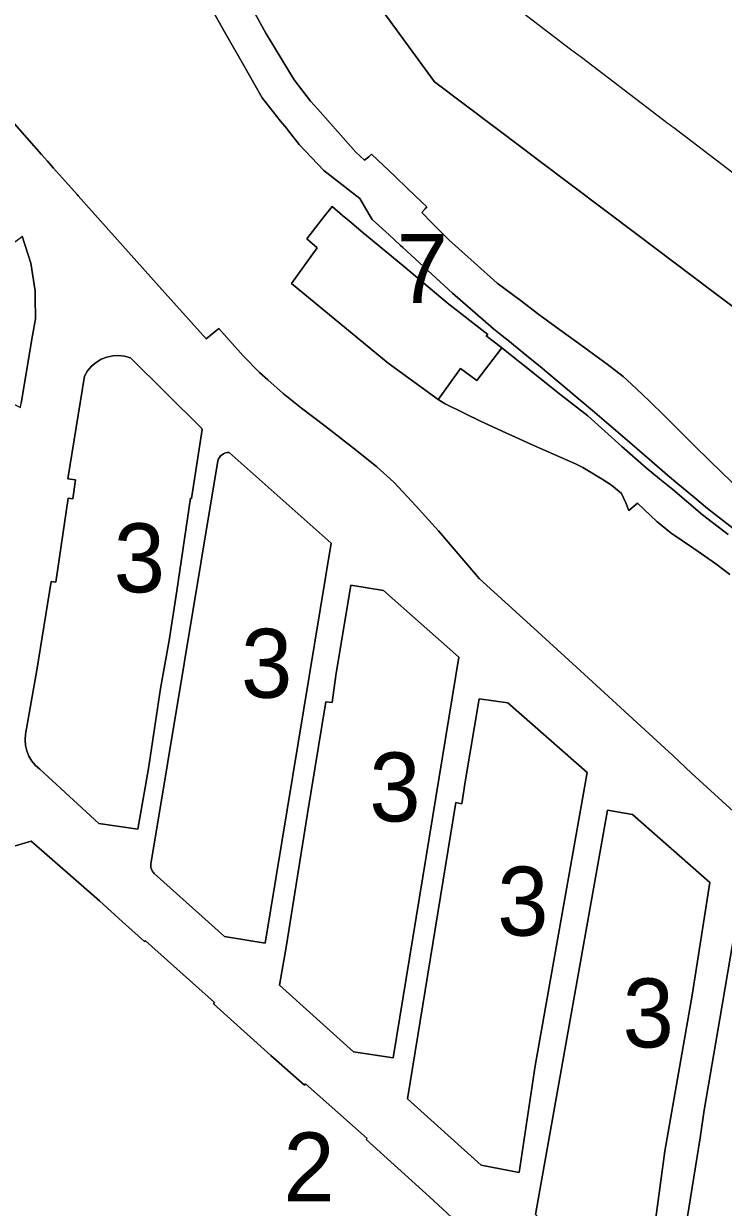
# Model space of a CAD drawing. Extents: x 598968 to 613553, y 4409678 to 4430833.
# Drawn here: x 607478.1 to 607599.8, y 4416479.9 to 4416685.8 of the extents above; entities that cross this region are included whole.
import ezdxf

# ---------------------------------------------------------------- set-up
doc = ezdxf.new("R2010")
doc.units = 0
for name, color, linetype in [('1', 7, 'Continuous'), ('ZONA 2. CARRERS DE CASES. Cases de trast', 7, 'Continuous'), ("ZONA 3. ILLES  D'EDIFICIS ENTRE MITGERES. EIXAMPLE.", 7, 'Continuous'), ('ZONA 7. CONJUNTS AMB ORDENACIONS ESPECÍFIQUES', 7, 'Continuous')]:
    doc.layers.add(name, color=color, linetype=linetype)

msp = doc.modelspace()

# ---------------------------------------------------------------- linework, layer by layer
at = {"layer": '1'}
for points in [[(607527.3672, 4416706.0991), (607549.5876, 4416675.6756), (607565.0673, 4416664.0096), (607567.5237, 4416662.1584), (607567.7321, 4416662.0015), (607584.8422, 4416649.1068), (607597.5962, 4416639.4965), (607608.9492, 4416630.9392)], [(607608.9492, 4416630.9392), (607597.5962, 4416639.4965), (607584.8422, 4416649.1068), (607567.7321, 4416662.0015), (607567.5237, 4416662.1584), (607565.0673, 4416664.0096), (607549.5876, 4416675.6756), (607527.3672, 4416706.0991)], [(607602.4415, 4416604.9807), (607599.6354, 4416607.6654), (607597.1873, 4416610.0078), (607595.0365, 4416612.131), (607592.1696, 4416615.0294), (607589.5868, 4416617.5946), (607587.0907, 4416620.0143), (607585.7848, 4416621.2802), (607583.8472, 4416623.0959), (607582.4373, 4416624.4167), (607579.6244, 4416626.5351), (607576.4249, 4416628.8801), (607576.3745, 4416628.917), (607570.7888, 4416632.9939), (607567.7575, 4416635.2064), (607564.4734, 4416637.6739), (607560.4776, 4416640.6762), (607556.4776, 4416644.2661), (607552.1594, 4416648.1558), (607550.3662, 4416649.9361), (607549.3387, 4416650.9565), (607549.1076, 4416651.1858), (607547.3976, 4416652.9658), (607547.9865, 4416653.6015), (607548.2776, 4416653.9158), (607547.3937, 4416654.7609), (607544.8997, 4416657.1461), (607542.7626, 4416659.1863), (607538.6677, 4416663.0955), (607538.1877, 4416662.6255), (607537.4077, 4416662.0455), (607535.9477, 4416663.4154), (607529.2969, 4416670.8985), (607528.0378, 4416672.3152), (607525.1978, 4416676.0151), (607520.2362, 4416684.1517), (607515.8654, 4416692.2057)], [(607515.8654, 4416692.2057), (607520.2362, 4416684.1517), (607525.1978, 4416676.0151), (607528.0378, 4416672.3152), (607529.2969, 4416670.8985), (607535.9477, 4416663.4154), (607537.4077, 4416662.0455), (607538.1877, 4416662.6255), (607538.6677, 4416663.0955), (607542.7626, 4416659.1863), (607544.8997, 4416657.1461), (607547.3937, 4416654.7609), (607548.2776, 4416653.9158), (607547.9865, 4416653.6015), (607547.3976, 4416652.9658), (607549.1076, 4416651.1858), (607549.3387, 4416650.9565), (607550.3662, 4416649.9361), (607552.1594, 4416648.1558), (607556.4776, 4416644.2661), (607560.4776, 4416640.6762), (607564.4734, 4416637.6739), (607567.7575, 4416635.2064), (607570.7888, 4416632.9939), (607576.3745, 4416628.917), (607576.4249, 4416628.8801), (607579.6244, 4416626.5351), (607582.4373, 4416624.4167), (607583.8472, 4416623.0959), (607585.7848, 4416621.2802), (607587.0907, 4416620.0143), (607589.5868, 4416617.5946), (607592.1696, 4416615.0294), (607595.0365, 4416612.131), (607597.1873, 4416610.0078), (607599.6354, 4416607.6654), (607602.4415, 4416604.9807)], [(607509.9029, 4416690.1297), (607513.2579, 4416684.0948), (607516.4329, 4416678.4949), (607519.6079, 4416672.895), (607522.8428, 4416668.8451), (607523.8895, 4416667.5348), (607523.964, 4416667.4416), (607526.0778, 4416664.7952), (607528.2128, 4416662.5153), (607530.3478, 4416660.2354), (607533.4878, 4416657.7955), (607534.0115, 4416657.3886), (607534.8207, 4416656.7598), (607536.6277, 4416655.3555), (607538.2554, 4416652.5999), (607538.7777, 4416651.7156), (607539.3614, 4416651.1822), (607541.7009, 4416649.0446), (607542.6627, 4416648.1658), (607543.6987, 4416647.2113), (607544.0839, 4416646.8564), (607552.7173, 4416638.9267), (607559.8877, 4416632.7264), (607561.2944, 4416631.5654), (607562.3662, 4416630.7129), (607565.5885, 4416628.0825), (607568.3513, 4416625.8622), (607569.1462, 4416625.1929), (607572.0004, 4416622.7896), (607574.5714, 4416620.6089), (607577.0665, 4416618.4943), (607579.9074, 4416616.0868), (607583.1155, 4416613.3085), (607585.2472, 4416611.4621), (607587.379, 4416609.6159), (607590.1373, 4416607.2271), (607591.9109, 4416605.7502), (607594.5084, 4416603.5873), (607597.1058, 4416601.4244), (607601.5051, 4416598.023)], [(607601.5051, 4416598.023), (607597.1058, 4416601.4244), (607594.5084, 4416603.5873), (607591.9109, 4416605.7502), (607590.1373, 4416607.2271), (607587.379, 4416609.6159), (607585.2472, 4416611.4621), (607583.1155, 4416613.3085), (607579.9074, 4416616.0868), (607577.0665, 4416618.4943), (607574.5714, 4416620.6089), (607572.0004, 4416622.7896), (607569.1462, 4416625.1929), (607568.3513, 4416625.8622), (607565.5885, 4416628.0825), (607562.3662, 4416630.7129), (607561.2944, 4416631.5654), (607559.8877, 4416632.7264), (607552.7173, 4416638.9267), (607544.0839, 4416646.8564), (607543.6987, 4416647.2113), (607542.6627, 4416648.1658), (607541.7009, 4416649.0446), (607539.3614, 4416651.1822), (607538.7777, 4416651.7156), (607538.2554, 4416652.5999), (607536.6277, 4416655.3555), (607534.8207, 4416656.7598), (607534.0115, 4416657.3886), (607533.4878, 4416657.7955), (607530.3478, 4416660.2354), (607528.2128, 4416662.5153), (607526.0778, 4416664.7952), (607523.964, 4416667.4416), (607523.8895, 4416667.5348), (607522.8428, 4416668.8451), (607519.6079, 4416672.895), (607516.4329, 4416678.4949), (607513.2579, 4416684.0948), (607509.9029, 4416690.1297)], [(607614.0479, 4416650.2438), (607591.2043, 4416667.6598), (607590.8733, 4416667.9122), (607590.5651, 4416668.1472), (607590.27, 4416668.3721), (607575.1528, 4416679.8974), (607573.2844, 4416681.3218), (607564.1252, 4416688.3032)], [(607606.9302, 4416543.8484), (607594.3303, 4416555.4268), (607591.0375, 4416558.4527), (607574.3176, 4416573.8472), (607566.2277, 4416581.212), (607557.4287, 4416589.2367), (607550.2878, 4416597.5465), (607548.0619, 4416600.044), (607546.4378, 4416601.8664), (607542.5078, 4416606.0563), (607539.5729, 4416608.6712), (607538.3435, 4416609.6678), (607535.5329, 4416611.9461), (607530.5529, 4416615.8009), (607526.478, 4416618.9008), (607523.268, 4416621.4708), (607520.608, 4416623.8057), (607519.178, 4416625.0956), (607516.3281, 4416627.9956), (607514.3881, 4416630.1705), (607512.1094, 4416632.7616), (607509.8781, 4416630.9454), (607501.7182, 4416640.0452), (607487.6315, 4416655.8444), (607487.4431, 4416656.0557), (607483.3545, 4416660.6414), (607482.2913, 4416661.8469), (607481.2278, 4416663.0529), (607465.8801, 4416680.4569)], [(607465.8801, 4416680.4569), (607481.2278, 4416663.0529), (607482.2913, 4416661.8469), (607483.3545, 4416660.6414), (607487.4431, 4416656.0557), (607487.6315, 4416655.8444), (607501.7182, 4416640.0452), (607509.8781, 4416630.9454), (607512.1094, 4416632.7616), (607514.3881, 4416630.1705), (607516.3281, 4416627.9956), (607519.178, 4416625.0956), (607520.608, 4416623.8057), (607523.268, 4416621.4708), (607526.478, 4416618.9008), (607530.5529, 4416615.8009), (607535.5329, 4416611.9461), (607538.3435, 4416609.6678), (607539.5729, 4416608.6712), (607542.5078, 4416606.0563), (607546.4378, 4416601.8664), (607548.0619, 4416600.044), (607550.2878, 4416597.5465), (607557.4287, 4416589.2367), (607566.2277, 4416581.212), (607574.3176, 4416573.8472), (607591.0375, 4416558.4527), (607594.3303, 4416555.4268), (607606.9302, 4416543.8484)], [(607600.9972, 4416589.9575), (607598.5573, 4416591.8274), (607594.6873, 4416594.5073), (607590.7573, 4416597.1472), (607588.2773, 4416599.1771), (607584.9174, 4416602.387), (607583.3774, 4416601.097), (607582.8874, 4416602.417), (607582.1374, 4416604.037), (607580.4074, 4416605.5269), (607578.7674, 4416606.5369), (607575.4029, 4416608.5568), (607574.1175, 4416609.2168), (607570.2925, 4416610.9017), (607566.4675, 4416612.5866), (607563.6876, 4416613.8565), (607562.0226, 4416614.6265), (607557.5776, 4416616.6664), (607554.9009, 4416617.9675), (607554.5227, 4416618.1513), (607551.4677, 4416619.6363), (607550.8627, 4416620.0212), (607550.2577, 4416620.4062), (607541.5602, 4416626.7512), (607524.7167, 4416640.6057), (607529.209, 4416646.7939), (607527.4007, 4416648.3765), (607528.9637, 4416650.3889), (607530.3467, 4416652.1694), (607531.7734, 4416654.0062), (607533.6047, 4416652.4378), (607534.7302, 4416651.474), (607536.8361, 4416649.6704), (607544.4235, 4416643.4316), (607551.7774, 4416637.2509), (607558.9014, 4416631.739), (607558.573, 4416631.4765), (607561.2428, 4416629.4431), (607561.2851, 4416629.4103), (607561.3304, 4416629.3747), (607567.5554, 4416624.387), (607571.0875, 4416621.5566), (607576.2974, 4416617.5867), (607582.1874, 4416612.2369), (607586.4273, 4416608.517), (607588.7473, 4416606.6271), (607591.0673, 4416604.7371), (607596.2172, 4416600.3573), (607600.6572, 4416596.8974)], [(607477.8784, 4416648.8046), (607479.3796, 4416644.1495), (607480.1589, 4416639.3209), (607480.1683, 4416638.1557), (607480.1985, 4416634.4299), (607479.6885, 4416631.5449), (607477.7042, 4416619.78)], [(607474.5055, 4416542.1323), (607479.441, 4416543.5718), (607491.3187, 4416533.1762), (607495.3486, 4416529.5363), (607499.1663, 4416526.0984), (607499.3086, 4416526.2564), (607511.3429, 4416515.4918), (607511.1685, 4416515.2968), (607521.1284, 4416506.2771), (607526.9784, 4416501.0972), (607527.1684, 4416501.3272), (607537.8683, 4416491.8274), (607537.7383, 4416491.6874), (607548.7182, 4416481.6777), (607554.1282, 4416476.7379)], [(607592.7577, 4416472.8886), (607595.282, 4416488.6863), (607595.7876, 4416491.9484), (607596.5276, 4416496.7985), (607599.2475, 4416512.6783), (607601.9874, 4416529.0282), (607605.8374, 4416528.6483), (607619.3972, 4416516.8086), (607613.5074, 4416480.6189), (607612.7174, 4416475.5589)]]:
    msp.add_lwpolyline(points, dxfattribs=at)
for points in [[(607454.2157, 4416631.5745), (607454.0687, 4416631.3444), (607467.0586, 4416624.4047), (607477.5785, 4416619.035), (607477.7042, 4416619.78), (607479.6885, 4416631.5449), (607480.1985, 4416634.4299), (607480.1683, 4416638.1557), (607480.1589, 4416639.3209), (607479.3796, 4416644.1495), (607477.8784, 4416648.8046), (607477.844, 4416648.7799), (607477.8941, 4416648.7225), (607454.2707, 4416631.5451)], [(607488.7184, 4416624.4851), (607489.2557, 4416625.3842), (607489.9321, 4416626.1838), (607490.7297, 4416626.8627), (607491.627, 4416627.4028), (607492.6003, 4416627.7898), (607493.6236, 4416628.0132), (607494.6696, 4416628.0671), (607495.7104, 4416627.95), (607496.7183, 4416627.6652), (607509.0782, 4416615.4256), (607509.2082, 4416615.2056), (607507.3483, 4416603.2057), (607507.1783, 4416603.2357), (607504.7683, 4416587.1058), (607503.4784, 4416578.4859), (607501.9684, 4416570.126), (607499.8485, 4416556.2161), (607497.9817, 4416545.6495), (607491.2186, 4416546.6261), (607480.9287, 4416556.1008), (607480.1839, 4416556.7478), (607479.5503, 4416557.504), (607479.0439, 4416558.3507), (607478.6772, 4416559.2666), (607478.4594, 4416560.2289), (607478.3961, 4416561.2135), (607478.4887, 4416562.1957), (607480.4387, 4416573.3456), (607482.9129, 4416588.7511), (607483.7186, 4416588.6155), (607485.9099, 4416603.2437), (607486.6735, 4416603.1191), (607487.1749, 4416606.4197), (607485.8185, 4416606.6153)], [(607511.9182, 4416609.7557), (607512.0354, 4416610.0599), (607512.1996, 4416610.3415), (607512.4066, 4416610.5934), (607512.6511, 4416610.809), (607512.9269, 4416610.9829), (607513.2268, 4416611.1106), (607513.5433, 4416611.1889), (607513.8682, 4416611.2157), (607531.628, 4416595.4062), (607520.1628, 4416525.8241), (607513.0985, 4416526.9867), (607500.8486, 4416537.9663), (607500.6468, 4416538.1827), (607500.4836, 4416538.4295), (607500.3635, 4416538.7), (607500.2898, 4416538.9865), (607500.2646, 4416539.2814), (607500.2886, 4416539.5763)], [(607532.4581, 4416572.3865), (607535.058, 4416588.1263), (607540.7479, 4416587.1965), (607553.8578, 4416575.5768), (607542.4182, 4416505.8774), (607535.4983, 4416506.9373), (607522.6584, 4416518.5269), (607523.8083, 4416525.1269), (607527.5082, 4416548.4067), (607530.6981, 4416567.8165), (607531.7757, 4416567.6787)], [(607554.9186, 4416553.8941), (607557.3878, 4416568.357), (607562.3378, 4416567.6371), (607576.1376, 4416555.5274), (607567.1129, 4416504.4879), (607564.348, 4416485.918), (607557.7181, 4416487.1878), (607544.8788, 4416498.7476), (607553.3079, 4416550.3171), (607554.3579, 4416550.0871)], [(607579.6918, 4416548.9945), (607584.0576, 4416548.2277), (607597.4675, 4416536.408), (607594.4076, 4416516.8082), (607589.6485, 4416489.6645), (607586.8878, 4416469.0585), (607586.5075, 4416468.4009), (607586.0264, 4416467.813), (607585.4571, 4416467.3101), (607584.8143, 4416466.9053), (607584.1149, 4416466.6092), (607583.3768, 4416466.4294), (607582.6195, 4416466.3705), (607581.8625, 4416466.4343), (607581.1257, 4416466.6189), (607580.4281, 4416466.9196), (607579.7879, 4416467.3284), (607577.8379, 4416468.8084), (607577.6879, 4416468.6584), (607567.168, 4416478.6381)]]:
    msp.add_lwpolyline(points, close=True, dxfattribs=at)
at = {"layer": 'ZONA 2. CARRERS DE CASES. Cases de trast'}
msp.add_lwpolyline([(607554.1282, 4416476.7379), (607548.7182, 4416481.6777), (607537.7383, 4416491.6874), (607537.8683, 4416491.8274), (607527.1684, 4416501.3272), (607526.9784, 4416501.0972), (607521.1284, 4416506.2771), (607511.1685, 4416515.2968), (607511.3429, 4416515.4918), (607499.3086, 4416526.2564), (607499.1663, 4416526.0984), (607495.3486, 4416529.5363), (607491.3187, 4416533.1762), (607479.441, 4416543.5718), (607474.5055, 4416542.1323)], dxfattribs=at)
at = {"layer": "ZONA 3. ILLES  D'EDIFICIS ENTRE MITGERES. EIXAMPLE."}
for points in [[(607509.2082, 4416615.2056), (607509.0782, 4416615.4256), (607496.7183, 4416627.6652), (607495.7104, 4416627.95), (607494.6696, 4416628.0671), (607493.6236, 4416628.0132), (607492.6003, 4416627.7898), (607491.627, 4416627.4028), (607490.7297, 4416626.8627), (607489.9321, 4416626.1838), (607489.2557, 4416625.3842), (607488.7184, 4416624.4851), (607485.8185, 4416606.6153), (607487.1749, 4416606.4197), (607486.6735, 4416603.1191), (607485.9099, 4416603.2437), (607483.7186, 4416588.6155), (607482.9129, 4416588.7511), (607480.4387, 4416573.3456), (607478.4887, 4416562.1957), (607478.3961, 4416561.2135), (607478.4594, 4416560.2289), (607478.6772, 4416559.2666), (607479.0439, 4416558.3507), (607479.5503, 4416557.504), (607480.1839, 4416556.7478), (607480.9287, 4416556.1008), (607491.2186, 4416546.6261), (607497.9817, 4416545.6495), (607499.8485, 4416556.2161), (607501.9684, 4416570.126), (607503.4784, 4416578.4859), (607504.7683, 4416587.1058), (607507.1783, 4416603.2357), (607507.3483, 4416603.2057)], [(607531.628, 4416595.4062), (607513.8682, 4416611.2157), (607513.5433, 4416611.1889), (607513.2268, 4416611.1106), (607512.9269, 4416610.9829), (607512.6511, 4416610.809), (607512.4066, 4416610.5934), (607512.1996, 4416610.3415), (607512.0354, 4416610.0599), (607511.9182, 4416609.7557), (607500.2886, 4416539.5763), (607500.2646, 4416539.2814), (607500.2898, 4416538.9865), (607500.3635, 4416538.7), (607500.4836, 4416538.4295), (607500.6468, 4416538.1827), (607500.8486, 4416537.9663), (607513.0985, 4416526.9867), (607520.1628, 4416525.8241)], [(607553.8578, 4416575.5768), (607540.7479, 4416587.1965), (607535.058, 4416588.1263), (607532.4581, 4416572.3865), (607531.7757, 4416567.6787), (607530.6981, 4416567.8165), (607527.5082, 4416548.4067), (607523.8083, 4416525.1269), (607522.6584, 4416518.5269), (607535.4983, 4416506.9373), (607542.4182, 4416505.8774)], [(607576.1376, 4416555.5274), (607562.3378, 4416567.6371), (607557.3878, 4416568.357), (607554.9186, 4416553.8941), (607554.3579, 4416550.0871), (607553.3079, 4416550.3171), (607544.8788, 4416498.7476), (607557.7181, 4416487.1878), (607564.348, 4416485.918), (607567.1129, 4416504.4879)], [(607586.8878, 4416469.0585), (607589.6485, 4416489.6645), (607594.4076, 4416516.8082), (607597.4675, 4416536.408), (607584.0576, 4416548.2277), (607579.6918, 4416548.9945), (607567.168, 4416478.6381), (607577.6879, 4416468.6584), (607577.8379, 4416468.8084), (607579.7879, 4416467.3284), (607580.4281, 4416466.9196), (607581.1257, 4416466.6189), (607581.8625, 4416466.4343), (607582.6195, 4416466.3705), (607583.3768, 4416466.4294), (607584.1149, 4416466.6092), (607584.8143, 4416466.9053), (607585.4571, 4416467.3101), (607586.0264, 4416467.813), (607586.5075, 4416468.4009)]]:
    msp.add_lwpolyline(points, close=True, dxfattribs=at)
msp.add_lwpolyline([(607612.7174, 4416475.5589), (607613.5074, 4416480.6189), (607619.3972, 4416516.8086), (607605.8374, 4416528.6483), (607601.9874, 4416529.0282), (607599.2475, 4416512.6783), (607596.5276, 4416496.7985), (607595.7876, 4416491.9484), (607595.282, 4416488.6863), (607592.7577, 4416472.8886)], dxfattribs=at)
at = {"layer": 'ZONA 7. CONJUNTS AMB ORDENACIONS ESPECÍFIQUES'}
msp.add_lwpolyline([(607561.3304, 4416629.3747), (607561.2851, 4416629.4103), (607561.2428, 4416629.4431), (607558.573, 4416631.4765), (607558.9014, 4416631.739), (607551.7774, 4416637.2509), (607544.4235, 4416643.4316), (607536.8361, 4416649.6704), (607534.7302, 4416651.474), (607533.6047, 4416652.4378), (607531.7734, 4416654.0062), (607530.3467, 4416652.1694), (607528.9637, 4416650.3889), (607527.4007, 4416648.3765), (607529.209, 4416646.7939), (607524.7167, 4416640.6057), (607541.5602, 4416626.7512), (607550.2577, 4416620.4062), (607550.3148, 4416620.4852), (607554.1376, 4416625.7762), (607556.9776, 4416623.7263)], close=True, dxfattribs=at)
msp.add_lwpolyline([(607600.6572, 4416596.8974), (607596.2172, 4416600.3573), (607591.0673, 4416604.7371), (607588.7473, 4416606.6271), (607586.4273, 4416608.517), (607582.1874, 4416612.2369), (607576.2974, 4416617.5867), (607571.0875, 4416621.5566), (607567.5554, 4416624.387), (607561.3304, 4416629.3747), (607556.9776, 4416623.7263), (607554.1376, 4416625.7762), (607550.3148, 4416620.4852), (607550.2577, 4416620.4062), (607550.8627, 4416620.0212), (607551.4677, 4416619.6363), (607554.5227, 4416618.1513), (607554.9009, 4416617.9675), (607557.5776, 4416616.6664), (607562.0226, 4416614.6265), (607563.6876, 4416613.8565), (607566.4675, 4416612.5866), (607570.2925, 4416610.9017), (607574.1175, 4416609.2168), (607575.4029, 4416608.5568), (607578.7674, 4416606.5369), (607580.4074, 4416605.5269), (607582.1374, 4416604.037), (607582.8874, 4416602.417), (607583.3774, 4416601.097), (607584.9174, 4416602.387), (607588.2773, 4416599.1771), (607590.7573, 4416597.1472), (607594.6873, 4416594.5073), (607598.5573, 4416591.8274), (607600.9972, 4416589.9575)], dxfattribs=at)

# ---------------------------------------------------------------- texts
at = {"layer": 'ZONA 2. CARRERS DE CASES. Cases de trast'}
msp.add_text('2', height=12, dxfattribs=at).set_placement((607523.3194, 4416480.895))
at = {"layer": "ZONA 3. ILLES  D'EDIFICIS ENTRE MITGERES. EIXAMPLE."}
for p in [(607493.8021, 4416586.8583), (607515.9463, 4416568.5199), (607538.2581, 4416547.0019), (607560.5082, 4416527.1375), (607582.3177, 4416507.6825)]:
    msp.add_text('3', height=12, dxfattribs=at).set_placement(p)
at = {"layer": 'ZONA 7. CONJUNTS AMB ORDENACIONS ESPECÍFIQUES'}
msp.add_text('7', height=12, dxfattribs=at).set_placement((607543.0236, 4416637.2062))

doc.saveas('drawing.dxf')
